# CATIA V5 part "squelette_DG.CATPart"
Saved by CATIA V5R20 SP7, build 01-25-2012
Part number: squelette_DG
Publications: "axe.pivot.D", "axe.pivot.E", "axe.pivot.G", "Plan.pivot.D", "barre_DG"
Bounding box of the stored display mesh (mm): x -17.9 to 2.1, y -52 to -21, z -9.5 to 59
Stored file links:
  F:\IAO\Catia\squelette_DG.CATPart
  F:\IAO\Catia\squelette.CATProduct
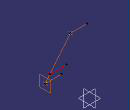
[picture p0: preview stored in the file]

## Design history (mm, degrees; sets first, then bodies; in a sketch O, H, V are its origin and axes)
Set1
  Plane1 "Plan.2,1": linked copy from another document
  Point1 "D": linked copy from another document
  Point2 "E": linked copy from another document
  Point3 "G": linked copy from another document
Set2
  Line1 "axe.pivot.D": type Normal, RefPoint Point1, RefSkin Plane1, Start 0, End 20
  Line2 "axe.pivot.E": type Normal, RefPoint Point2, RefSkin Plane1, Start 0, End 20
  Line3 "axe.pivot.G": type Normal, RefPoint Point3, RefSkin Plane1, Start 0, End 20
  Plane2 "Plan.pivot.D": type Offset, RefPlane Plane1, Offset 0
  Line4 "barre_DG": type PtPt, FirstPoint Point1, SecondPoint Point3
Body1 (main body)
